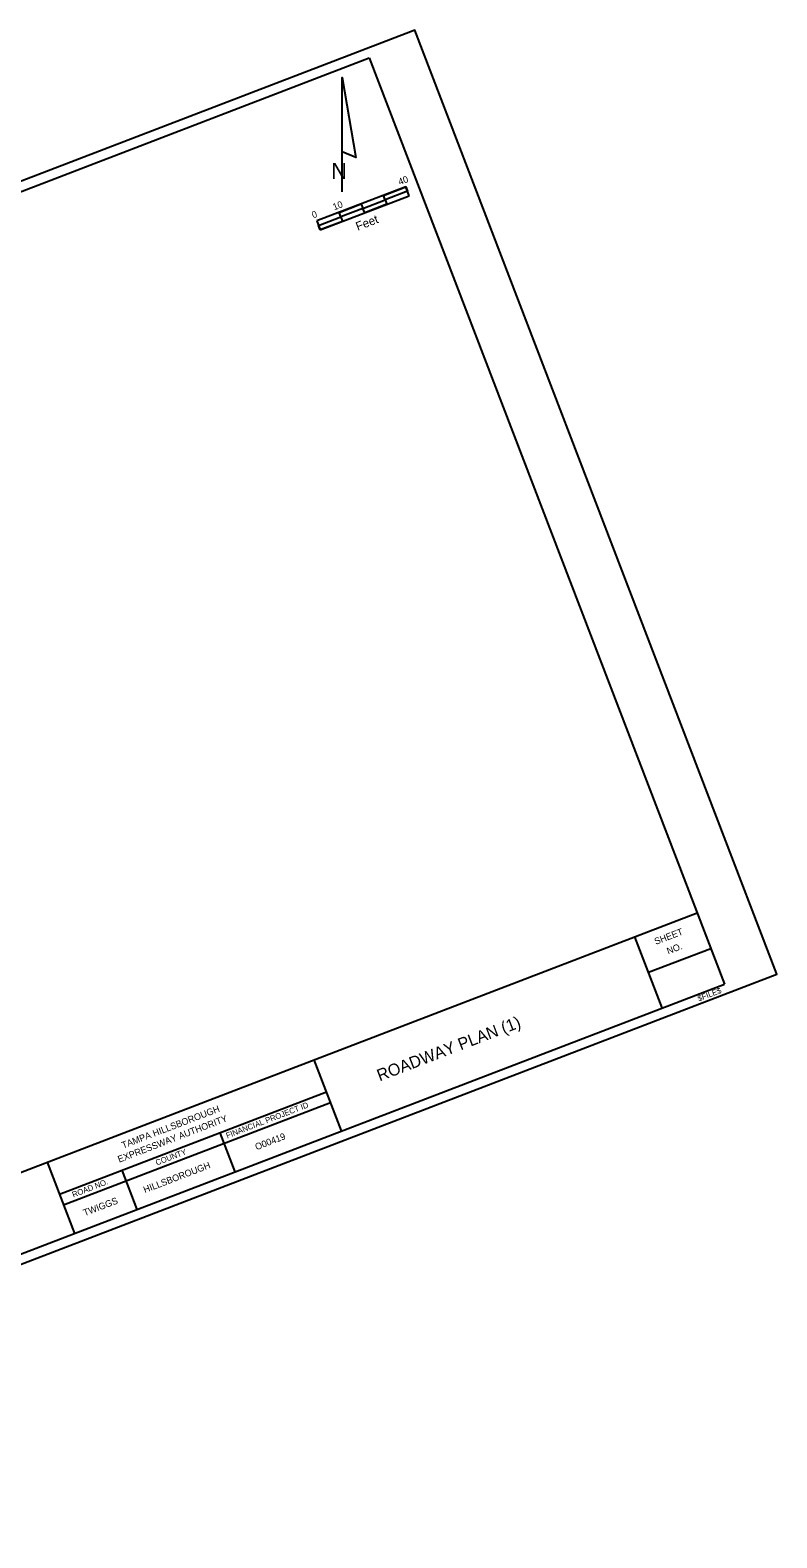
# Model space of a CAD drawing. Extents: x 510230 to 510998, y 1315131 to 1315763.
# Drawn here: x 510685 to 510998, y 1315131 to 1315763 of the extents above; entities that cross this region are included whole.
import ezdxf

# ---------------------------------------------------------------- set-up
doc = ezdxf.new("R2010")
doc.units = 0
for name, color, linetype in [('DirArrowsPavt', 7, 'Continuous'), ('NorthArw_dp', 7, 'Continuous'), ('Scale_dp', 7, 'Continuous'), ('SignPanel', 7, 'Continuous'), ('TextLabel', 7, 'Continuous'), ('TextMisc', 7, 'Continuous')]:
    doc.layers.add(name, color=color, linetype=linetype)

msp = doc.modelspace()

# ---------------------------------------------------------------- linework, layer by layer
at = {"layer": 'DirArrowsPavt'}
for p, q in [((510949.75, 1315353.28), (510938.29, 1315383.16)), ((510944.02, 1315368.22), (510970.17, 1315378.25)), ((510815.31, 1315301.7), (510803.85, 1315331.58)), ((510696.97, 1315275.15), (510809, 1315318.13)), ((510698.69, 1315270.67), (510810.72, 1315313.65)), ((510764.19, 1315300.94), (510770.49, 1315284.51)), ((510691.81, 1315288.6), (510703.27, 1315258.72)), ((510723.11, 1315285.18), (510729.41, 1315268.75))]:
    msp.add_line(p, q, dxfattribs=at)
at = {"layer": 'NorthArw_dp'}
msp.add_line((510815.54, 1315695.5), (510815.54, 1315743.5), dxfattribs=at)
msp.add_lwpolyline([(510815.54, 1315712.3), (510815.54, 1315743.5), (510821.3, 1315709.9)], close=True, dxfattribs=at)
at = {"layer": 'Scale_dp'}
for p, q in [((510842.23, 1315697.62), (510804.88, 1315683.29)), ((510843.66, 1315693.88), (510842.23, 1315697.62)), ((510806.31, 1315679.56), (510843.66, 1315693.88)), ((510804.88, 1315683.29), (510806.31, 1315679.56))]:
    msp.add_line(p, q, dxfattribs=at)
for points in [[(510833.61, 1315692.17), (510832.89, 1315694.04), (510842.23, 1315697.62), (510842.94, 1315695.75)], [(510814.93, 1315685.01), (510814.22, 1315686.87), (510823.55, 1315690.46), (510824.27, 1315688.59)], [(510824.99, 1315686.72), (510824.27, 1315688.59), (510833.61, 1315692.17), (510834.32, 1315690.3)], [(510806.31, 1315679.56), (510805.6, 1315681.42), (510814.93, 1315685.01), (510815.65, 1315683.14)]]:
    msp.add_lwpolyline(points, close=True, dxfattribs=at)
at = {"layer": 'SignPanel'}
msp.add_lwpolyline([(510381.66, 1315131.05), (510997.87, 1315367.46), (510846, 1315763.32), (510229.79, 1315526.92)], close=True, dxfattribs=at)
at = {"layer": 'TextLabel'}
for p, q in [((510251.76, 1315531.07), (510826.89, 1315751.71)), ((510826.89, 1315751.71), (510975.9, 1315363.31)), ((510389.31, 1315172.55), (510964.44, 1315393.19)), ((510400.77, 1315142.67), (510975.9, 1315363.31))]:
    msp.add_line(p, q, dxfattribs=at)

# ---------------------------------------------------------------- texts
at = {"layer": 'NorthArw_dp'}
msp.add_text('N', height=6.72, dxfattribs=at).set_placement((510810.98, 1315700.94))
msp.add_text('$FILE$', height=2.4, rotation=20.98867, dxfattribs=at).set_placement((510965.19, 1315355.98))
at = {"layer": 'Scale_dp'}
for s, height, p in [('40', 2.8, (510839.7, 1315698.26)), ('10', 2.8, (510812.23, 1315687.72)), ('0', 2.8, (510803.42, 1315684.34)), ('Feet', 3.6, (510822.07, 1315679.17))]:
    msp.add_text(s, height=height, rotation=20.98867, dxfattribs=at).set_placement(p)
at = {"layer": 'TextLabel'}
for s, p in [('TAMPA HILLSBOROUGH', (510723.68, 1315294.24)), ('EXPRESSWAY AUTHORITY', (510722.05, 1315288.36))]:
    msp.add_text(s, height=2.8, rotation=20.98867, dxfattribs=at).set_placement(p)
at = {"layer": 'TextMisc'}
for s, height, rotation, p in [('SHEET', 2.8, 20.84933, (510947.11, 1315379.71)), ('NO.', 2.8, 20.84933, (510952.31, 1315375.7)), ('       ROADWAY PLAN (1)        ', 5, 20.98867, (510819.14, 1315317.77)), ('FINANCIAL PROJECT ID', 2.4, 20.98867, (510767.36, 1315298.52)), ('    O00419    ', 2.8, 20.98867, (510775.76, 1315292.08)), ('COUNTY', 2.4, 20.98867, (510737.81, 1315287.18)), ('HILLSBOROUGH', 2.8, 20.98867, (510732.79, 1315275.6)), ('ROAD NO.', 2.4, 20.98867, (510702.81, 1315273.76)), ('TWIGGS ', 2.8, 20.98867, (510707.58, 1315265.93))]:
    msp.add_text(s, height=height, rotation=rotation, dxfattribs=at).set_placement(p)

doc.saveas('drawing.dxf')
